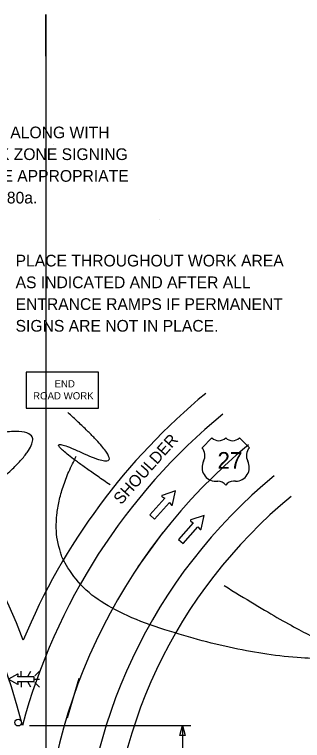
# Model space of a CAD drawing. Extents: x 16728 to 18475, y 6981 to 8243.
# Drawn here: x 17001.3 to 17173.4, y 7808.9 to 8243.2 of the extents above; entities that cross this region are included whole.
import ezdxf

# ---------------------------------------------------------------- set-up
doc = ezdxf.new("R2010")
doc.units = 0
for name, color, linetype in [('ALI_LEGAL_EX', 7, 'Continuous'), ('MT_SCRATCH_LEVEL_E', 7, 'Continuous'), ('PAVT_EDGE_EX', 7, 'Continuous'), ('TRAFFIC_SIGNS_PR', 7, 'Continuous'), ('TYPICAL_EX', 7, 'Continuous'), ('TYPICAL_TEXT_DIMEN_PR', 7, 'Continuous')]:
    doc.layers.add(name, color=color, linetype=linetype)

msp = doc.modelspace()

# ---------------------------------------------------------------- linework, layer by layer
at = {"layer": 'ALI_LEGAL_EX'}
for p, q in [((17019.95, 8243.16), (17019.95, 7482.4)), ((17039.84, 7845.95), (17032.85, 7822.29))]:
    msp.add_line(p, q, dxfattribs=at)
for points in [[(17019.95, 8218.16), (17019.95, 8243.16)], [(17075.14, 7912.84), (17089.89, 7933.02)]]:
    msp.add_lwpolyline(points, dxfattribs=at)
msp.add_arc((17357.65, 7723.56), 340, 129.5666, 180, dxfattribs=at)
at = {"layer": 'MT_SCRATCH_LEVEL_E'}
for p, q in [((17097.48, 7958.2), (17089.6, 7955.52)), ((17097.48, 7958.2), (17089.6, 7955.52)), ((17095.77, 7950.04), (17097.48, 7958.2)), ((17095.77, 7950.04), (17097.48, 7958.2)), ((17091.04, 7953.75), (17082.24, 7943.84)), ((17091.04, 7953.75), (17082.24, 7943.84)), ((17089.5, 7954.69), (17091.04, 7953.75)), ((17089.5, 7954.69), (17091.04, 7953.75)), ((17085.03, 7941.35), (17093.84, 7951.26)), ((17085.03, 7941.35), (17093.84, 7951.26)), ((17093.84, 7951.26), (17094.96, 7949.84)), ((17093.84, 7951.26), (17094.96, 7949.84)), ((17082.24, 7943.84), (17085.03, 7941.35)), ((17082.24, 7943.84), (17085.03, 7941.35)), ((17114.56, 7943.55), (17106.68, 7940.86)), ((17114.56, 7943.55), (17106.68, 7940.86)), ((17112.85, 7935.38), (17114.56, 7943.55)), ((17112.85, 7935.38), (17114.56, 7943.55)), ((17108.12, 7939.09), (17099.32, 7929.18)), ((17108.12, 7939.09), (17099.32, 7929.18)), ((17106.59, 7940.03), (17108.12, 7939.09)), ((17106.59, 7940.03), (17108.12, 7939.09)), ((17102.12, 7926.69), (17110.92, 7936.6)), ((17102.12, 7926.69), (17110.92, 7936.6)), ((17110.92, 7936.6), (17112.04, 7935.19)), ((17110.92, 7936.6), (17112.04, 7935.19)), ((17099.32, 7929.18), (17102.12, 7926.69)), ((17099.32, 7929.18), (17102.12, 7926.69))]:
    msp.add_line(p, q, dxfattribs=at)
for centre, start, end in [((17089.75, 7955.08), 108.8029, 238.3418), ((17089.75, 7955.08), 108.8029, 238.3418), ((17095.32, 7950.14), 218.4142, 348.1511), ((17095.32, 7950.14), 218.4142, 348.1511), ((17106.84, 7940.43), 108.8029, 238.3418), ((17106.84, 7940.43), 108.8029, 238.3418), ((17112.4, 7935.48), 218.4142, 348.1511), ((17112.4, 7935.48), 218.4142, 348.1511)]:
    msp.add_arc(centre, 0.463, start, end, dxfattribs=at)
at = {"layer": 'PAVT_EDGE_EX'}
for centre, radius, start, end in [((16629.65, 7723.56), 404, 21.0961, 70.3484), ((16629.65, 7723.56), 388, 14.0482, 70.3484), ((17357.65, 7723.56), 380, 129.5666, 157.5011), ((17357.65, 7723.56), 364, 129.5666, 165.0045), ((17357.65, 7723.56), 316, 129.5666, 180), ((17357.65, 7723.56), 300, 129.5666, 180)]:
    msp.add_arc(centre, radius, start, end, dxfattribs=at)
at = {"layer": 'TRAFFIC_SIGNS_PR'}
for p, q in [((17005.38, 7847.57), (17005.38, 7850.39)), ((17009.51, 7847.57), (17011.14, 7850.39)), ((17013.47, 7847.57), (17016.29, 7850.39)), ((17005.38, 7843.5), (17005.38, 7840.68)), ((17011.17, 7840.68), (17009.54, 7843.5)), ((17013.47, 7845.53), (17016.29, 7845.53)), ((17013.47, 7843.5), (17016.29, 7840.68))]:
    msp.add_line(p, q, dxfattribs=at)
msp.add_lwpolyline([(17008.37, 8007.58), (17051.57, 8007.58), (17051.57, 8029.18), (17008.37, 8029.18)], close=True, dxfattribs=at)
for points in [[(17003.05, 7848.55), (16997.74, 7845.53), (17003.05, 7842.49)], [(17003.55, 7842.85), (17003.32, 7844.15), (17013.05, 7844.15), (17013.05, 7846.89), (17003.32, 7846.89), (17003.56, 7848.19)]]:
    msp.add_lwpolyline(points, dxfattribs=at)
msp.add_circle((17003.5, 7819.57), 2, dxfattribs=at)
for centre, start, end in [((17003.22, 7848.25), 350.7308, 118.8916), ((17003.22, 7842.79), 241.4833, 9.9593)]:
    msp.add_arc(centre, 0.341, start, end, dxfattribs=at)
at = {"layer": 'TYPICAL_EX'}
for p, q in [((17113.35, 7983.99), (17119.24, 7989.88)), ((17141.65, 7983.99), (17135.75, 7989.88)), ((17121.59, 7963.93), (17122.77, 7963.93)), ((17133.4, 7963.93), (17132.22, 7963.93))]:
    msp.add_line(p, q, dxfattribs=at)
for centre, radius, start, end in [((17123.37, 7994.18), 5.96, 226.1404, 313.8596), ((17131.62, 7994.18), 5.96, 226.1404, 313.8596), ((17107.76, 7979.27), 7.31, 333.0977, 40.1936), ((17147.23, 7979.27), 7.31, 139.8064, 206.9023), ((17121.61, 7972.17), 8.24, 152.6698, 269.9013), ((17133.38, 7972.17), 8.24, 270.0987, 27.3302), ((17122.79, 7958.02), 5.91, 37.1038, 90.1385), ((17132.21, 7958.02), 5.91, 89.8615, 142.8962)]:
    msp.add_arc(centre, radius, start, end, dxfattribs=at)
at = {"layer": 'TYPICAL_TEXT_DIMEN_PR'}
for p, q in [((17010.2, 7817.74), (17106.65, 7817.74)), ((17100.08, 7811.88), (17101.65, 7817.74)), ((17101.65, 7817.74), (17103.22, 7811.88)), ((17101.65, 7817.74), (17101.65, 7767.74)), ((17101.65, 7811.88), (17100.08, 7811.88)), ((17103.22, 7811.88), (17101.65, 7811.88))]:
    msp.add_line(p, q, dxfattribs=at)
for points in [[(17024.7, 8165.38), (17024.71, 8165.39), (17024.71, 8165.4), (17024.71, 8165.4)], [(17087.8, 8120.33), (17087.81, 8120.33), (17087.82, 8120.33), (17087.82, 8120.33)], [(16972.79, 7948.45), (17048.35, 8006.24), (16909.74, 7974.41), (16969.14, 8031.74)], [(17058.5, 7961.72), (17006.47, 7997.19), (17077.79, 7964.45), (17033.17, 8005.08)], [(17221.94, 7861.33), (17166.62, 7849.44), (17000.13, 7906.03), (17038.24, 7978.99)], [(17126.63, 7901.54), (17216.29, 7845.78), (17166.16, 7906.16), (17227.39, 7901.54)]]:
    msp.add_open_spline(points, degree=2, dxfattribs=at)

# ---------------------------------------------------------------- texts
at = {"layer": 'TRAFFIC_SIGNS_PR'}
for s, height, p in [('PLACE THESE SIGNS ALONG WITH', 7, (16899.98, 8169.11)), ('THE ADVANCE WORK ZONE SIGNING', 7, (16899.98, 8156.11)), ('AS DEPICTED ON THE APPROPRIATE', 7, (16899.98, 8143.11)), ('TYPICAL M0030a-M0080a.', 7, (16899.98, 8130.11)), ('PLACE THROUGHOUT WORK AREA', 7, (17001.98, 8092.44)), ('AS INDICATED AND AFTER ALL', 7, (17001.98, 8079.44)), ('ENTRANCE RAMPS IF PERMANENT', 7, (17001.98, 8066.44)), ('SIGNS ARE NOT IN PLACE.', 7, (17001.98, 8053.44)), ('END', 4.31, (17025.25, 8020.1)), ('ROAD WORK', 4.31, (17012.43, 8012.92))]:
    msp.add_text(s, height=height, dxfattribs=at).set_placement(p)
at = {"layer": 'TYPICAL_EX'}
msp.add_text('27', height=10, dxfattribs=at).set_placement((17122.61, 7971.41))
at = {"layer": 'TYPICAL_TEXT_DIMEN_PR'}
msp.add_text('SHOULDER', height=7, rotation=48.378, dxfattribs=at).set_placement((17065, 7949.51))

doc.saveas('drawing.dxf')
